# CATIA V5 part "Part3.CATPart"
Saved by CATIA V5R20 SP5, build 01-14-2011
Part number: Part3
Bounding box of the stored display mesh (mm): x -55.246 to 55.246, y -55.075 to 55.075, z 4.617 to 129.748
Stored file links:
  C:\Documents and Settings\Student\桌面\考试\Part3.CATPart
  C:\Program Files\Dassault Systemes\B20\intel_a\startup\materials\Catalog.CATMaterial
  C:\Program Files\Dassault Systemes\B20\intel_a\startup\materials\fence_1.jpg
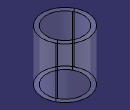
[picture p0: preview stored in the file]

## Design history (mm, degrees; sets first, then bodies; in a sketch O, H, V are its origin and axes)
Body1 (main body)
  Sketch1 on zx-plane, origin (0, 0, 0), H (-1, 0, 0), V (0, 0, 1)
    line L1 (45, 129.7479) -> (55.246, 129.7479)
    line L2 (55.246, 129.7479) -> (55.246, 4.6167)
    line L3 (55.246, 4.6167) -> (45, 4.6167)
    line L4 (45, 4.6167) -> (45, 129.7479)
    distance V L4 = 45
    horizontal: L1 H, L3 H
    vertical: L2 V, L4 V
  Shaft1: profile Sketch1, axis Sketch1.V, angle 360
